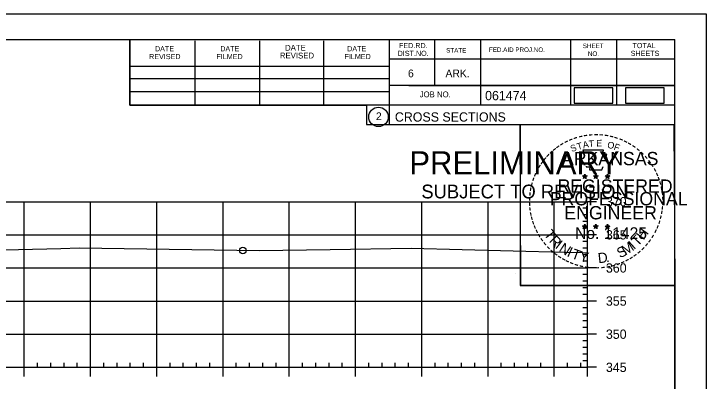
# Model space of a CAD drawing. Extents: x 1359801 to 1362404, y 372415 to 374228.
# Drawn here: x 1361262.1 to 1361366.6, y 373105.8 to 373161.3 of the extents above; entities that cross this region are included whole.
import ezdxf

# ---------------------------------------------------------------- set-up
doc = ezdxf.new("R2010")
doc.units = 0
for name, color, linetype in [('S_DRG_PT_SYM', 7, 'Continuous'), ('S_MAILBOX', 7, 'Continuous'), ('S_PRIMARY_CTL', 7, 'Continuous'), ('S_PRIMARY_CTL_ANNOT', 7, 'Continuous'), ('S_SHOULDER', 7, 'Continuous'), ('S_TELEPHONE_UTILITIES', 7, 'Continuous'), ('S_UNDERGROUND_CABLE', 7, 'Continuous'), ('S_UTL_PT_SYM', 7, 'Continuous'), ('S_WATER_UTILITIES', 7, 'Continuous')]:
    doc.layers.add(name, color=color, linetype=linetype)

msp = doc.modelspace()

# ---------------------------------------------------------------- linework, layer by layer
at = {"layer": 'S_DRG_PT_SYM'}
msp.add_lwpolyline([(1361245.69, 373125.3), (1361269.23, 373125.87), (1361272.01, 373125.94), (1361275.39, 373125.89), (1361299.18, 373125.53), (1361309.87, 373125.71), (1361322.12, 373125.9), (1361345.23, 373125.31), (1361347.93, 373125.24), (1361348.33, 373125.22), (1361348.71, 373125.21)], dxfattribs=at)
at = {"layer": 'S_MAILBOX'}
for p, q in [((1361058.71, 373132.92), (1361348.71, 373132.92)), ((1361058.71, 373132.92), (1361348.71, 373132.92)), ((1361263.71, 373107.92), (1361263.71, 373132.92)), ((1361263.71, 373107.92), (1361263.71, 373132.92)), ((1361273.71, 373107.92), (1361273.71, 373132.92)), ((1361273.71, 373107.92), (1361273.71, 373132.92)), ((1361283.71, 373107.92), (1361283.71, 373132.92)), ((1361283.71, 373107.92), (1361283.71, 373132.92)), ((1361293.71, 373107.92), (1361293.71, 373132.92)), ((1361293.71, 373107.92), (1361293.71, 373132.92)), ((1361303.71, 373107.92), (1361303.71, 373132.92)), ((1361303.71, 373107.92), (1361303.71, 373132.92)), ((1361313.71, 373107.92), (1361313.71, 373132.92)), ((1361313.71, 373107.92), (1361313.71, 373132.92)), ((1361323.71, 373107.92), (1361323.71, 373132.92)), ((1361323.71, 373107.92), (1361323.71, 373132.92)), ((1361333.71, 373107.92), (1361333.71, 373132.92)), ((1361333.71, 373107.92), (1361333.71, 373132.92)), ((1361343.71, 373107.92), (1361343.71, 373132.92)), ((1361343.71, 373107.92), (1361343.71, 373132.92)), ((1361348.71, 373107.92), (1361348.71, 373132.92)), ((1361348.71, 373107.92), (1361348.71, 373132.92)), ((1361058.71, 373127.92), (1361348.71, 373127.92)), ((1361058.71, 373127.92), (1361348.71, 373127.92)), ((1361058.71, 373122.92), (1361348.71, 373122.92)), ((1361058.71, 373122.92), (1361348.71, 373122.92)), ((1361058.71, 373117.92), (1361348.71, 373117.92)), ((1361058.71, 373117.92), (1361348.71, 373117.92)), ((1361058.71, 373112.92), (1361348.71, 373112.92)), ((1361058.71, 373112.92), (1361348.71, 373112.92)), ((1361058.71, 373107.92), (1361348.71, 373107.92)), ((1361058.71, 373107.92), (1361348.71, 373107.92))]:
    msp.add_line(p, q, dxfattribs=at)
at = {"layer": 'S_SHOULDER'}
for p, q in [((1361033.31, 373161.28), (1361366.64, 373161.28)), ((1361337.92, 373122.13), (1361337.92, 373122.13))]:
    msp.add_line(p, q, dxfattribs=at)
for points in [[(1361033.3, 373161.28), (1361366.64, 373161.28), (1361366.64, 372947.94), (1361033.3, 372947.94)], [(1361279.63, 373157.38), (1361279.63, 373147.5), (1361315.36, 373147.5), (1361315.36, 373144.58), (1361338.56, 373144.58), (1361338.56, 373120.25), (1361361.89, 373120.25), (1361361.89, 372951.92), (1361045.71, 372951.92), (1361045.71, 373157.38)], [(1361338.56, 373144.58), (1361361.77, 373144.58), (1361361.89, 373120.25), (1361338.68, 373120.25)]]:
    msp.add_lwpolyline(points, close=True, dxfattribs=at)
msp.add_circle((1361296.69, 373125.57), 0.5, dxfattribs=at)
at = {"layer": 'S_TELEPHONE_UTILITIES'}
for p, q in [((1361347.98, 373136.84), (1361348.32, 373136.73)), ((1361347.98, 373136.84), (1361348.23, 373136.79)), ((1361347.98, 373136.84), (1361348.21, 373136.71)), ((1361348.11, 373136.43), (1361348.32, 373136.73)), ((1361348.11, 373136.43), (1361348.23, 373136.67)), ((1361348.11, 373136.43), (1361348.32, 373136.65)), ((1361348.32, 373137.09), (1361348.28, 373136.84)), ((1361348.32, 373136.73), (1361348.32, 373137.09)), ((1361348.32, 373137.09), (1361348.37, 373136.84)), ((1361348.67, 373136.84), (1361348.32, 373136.73)), ((1361348.54, 373136.43), (1361348.32, 373136.73)), ((1361348.54, 373136.43), (1361348.32, 373136.64)), ((1361348.67, 373136.84), (1361348.39, 373136.79)), ((1361348.54, 373136.43), (1361348.4, 373136.72)), ((1361348.67, 373136.84), (1361348.47, 373136.73)), ((1361349.65, 373136.84), (1361349.99, 373136.73)), ((1361349.65, 373136.84), (1361349.9, 373136.79)), ((1361349.65, 373136.84), (1361349.88, 373136.71)), ((1361349.78, 373136.43), (1361349.99, 373136.73)), ((1361349.78, 373136.43), (1361349.9, 373136.67)), ((1361349.78, 373136.43), (1361349.99, 373136.65)), ((1361349.99, 373137.09), (1361349.95, 373136.84)), ((1361349.99, 373136.73), (1361349.99, 373137.09)), ((1361349.99, 373137.09), (1361350.04, 373136.84)), ((1361350.34, 373136.84), (1361349.99, 373136.73)), ((1361350.21, 373136.43), (1361349.99, 373136.73)), ((1361350.21, 373136.43), (1361349.99, 373136.64)), ((1361350.34, 373136.84), (1361350.06, 373136.79)), ((1361350.21, 373136.43), (1361350.07, 373136.72)), ((1361350.34, 373136.84), (1361350.14, 373136.73)), ((1361351.41, 373136.82), (1361351.76, 373136.71)), ((1361351.41, 373136.82), (1361351.66, 373136.78)), ((1361351.41, 373136.82), (1361351.65, 373136.7)), ((1361351.54, 373136.42), (1361351.76, 373136.71)), ((1361351.54, 373136.42), (1361351.67, 373136.66)), ((1361351.54, 373136.42), (1361351.76, 373136.63)), ((1361351.76, 373137.08), (1361351.72, 373136.83)), ((1361351.76, 373136.71), (1361351.76, 373137.08)), ((1361351.76, 373137.08), (1361351.81, 373136.83)), ((1361352.11, 373136.82), (1361351.76, 373136.71)), ((1361351.97, 373136.42), (1361351.76, 373136.71)), ((1361351.97, 373136.42), (1361351.76, 373136.63)), ((1361352.11, 373136.82), (1361351.82, 373136.78)), ((1361351.97, 373136.42), (1361351.83, 373136.71)), ((1361352.11, 373136.82), (1361351.9, 373136.72)), ((1361347.97, 373129.26), (1361348.32, 373129.15)), ((1361347.97, 373129.26), (1361348.22, 373129.22)), ((1361347.97, 373129.26), (1361348.21, 373129.14)), ((1361348.1, 373128.86), (1361348.32, 373129.15)), ((1361348.1, 373128.86), (1361348.23, 373129.1)), ((1361348.32, 373129.52), (1361348.28, 373129.27)), ((1361348.32, 373129.15), (1361348.32, 373129.52)), ((1361348.32, 373129.52), (1361348.37, 373129.27)), ((1361348.67, 373129.26), (1361348.32, 373129.15)), ((1361348.53, 373128.86), (1361348.32, 373129.15)), ((1361348.67, 373129.26), (1361348.38, 373129.21)), ((1361348.53, 373128.86), (1361348.4, 373129.15)), ((1361348.67, 373129.26), (1361348.46, 373129.16)), ((1361349.64, 373129.26), (1361349.99, 373129.15)), ((1361349.64, 373129.26), (1361349.89, 373129.22)), ((1361349.64, 373129.26), (1361349.88, 373129.14)), ((1361349.77, 373128.86), (1361349.99, 373129.15)), ((1361349.77, 373128.86), (1361349.9, 373129.1)), ((1361349.99, 373129.52), (1361349.95, 373129.27)), ((1361349.99, 373129.15), (1361349.99, 373129.52)), ((1361349.99, 373129.52), (1361350.04, 373129.27)), ((1361350.34, 373129.26), (1361349.99, 373129.15)), ((1361350.2, 373128.86), (1361349.99, 373129.15)), ((1361350.34, 373129.26), (1361350.05, 373129.21)), ((1361350.2, 373128.86), (1361350.07, 373129.15)), ((1361350.34, 373129.26), (1361350.13, 373129.16)), ((1361351.41, 373129.25), (1361351.76, 373129.14)), ((1361351.41, 373129.25), (1361351.66, 373129.21)), ((1361351.41, 373129.25), (1361351.64, 373129.13)), ((1361351.54, 373128.85), (1361351.76, 373129.14)), ((1361351.76, 373129.51), (1361351.72, 373129.26)), ((1361351.76, 373129.14), (1361351.76, 373129.51)), ((1361351.76, 373129.51), (1361351.81, 373129.26)), ((1361352.1, 373129.25), (1361351.76, 373129.14)), ((1361351.97, 373128.85), (1361351.76, 373129.14)), ((1361352.1, 373129.25), (1361351.82, 373129.2)), ((1361351.97, 373128.85), (1361351.83, 373129.14)), ((1361352.1, 373129.25), (1361351.9, 373129.15)), ((1361348.1, 373128.86), (1361348.32, 373129.07)), ((1361348.53, 373128.86), (1361348.32, 373129.07)), ((1361349.77, 373128.86), (1361349.99, 373129.07)), ((1361350.2, 373128.86), (1361349.99, 373129.07)), ((1361351.54, 373128.85), (1361351.67, 373129.09)), ((1361351.54, 373128.85), (1361351.75, 373129.06)), ((1361351.97, 373128.85), (1361351.75, 373129.06))]:
    msp.add_line(p, q, dxfattribs=at)
for points in [[(1361348.02, 373140.71), (1361348.29, 373139.89)], [(1361351.53, 373139.79), (1361351.67, 373140.08), (1361350.98, 373140.05), (1361351.13, 373140.71), (1361348.02, 373140.71)], [(1361348.51, 373138.29), (1361348.51, 373138.2), (1361349.07, 373138.19), (1361349.02, 373137.71), (1361350.89, 373137.71), (1361351.09, 373138.25)], [(1361348.32, 373137.09), (1361348.54, 373136.43), (1361347.98, 373136.84), (1361348.67, 373136.84), (1361348.11, 373136.43), (1361348.32, 373137.09)], [(1361349.99, 373137.09), (1361350.21, 373136.43), (1361349.65, 373136.84), (1361350.34, 373136.84), (1361349.78, 373136.43), (1361349.99, 373137.09)], [(1361351.76, 373137.08), (1361351.97, 373136.42), (1361351.41, 373136.82), (1361352.11, 373136.82), (1361351.54, 373136.42), (1361351.76, 373137.08)], [(1361348.32, 373129.52), (1361348.53, 373128.86), (1361347.97, 373129.26), (1361348.67, 373129.26), (1361348.1, 373128.86), (1361348.32, 373129.52)], [(1361349.99, 373129.52), (1361350.2, 373128.86), (1361349.64, 373129.26), (1361350.34, 373129.26), (1361349.77, 373128.86), (1361349.99, 373129.52)], [(1361351.76, 373129.51), (1361351.97, 373128.85), (1361351.41, 373129.25), (1361352.1, 373129.25), (1361351.54, 373128.85), (1361351.76, 373129.51)]]:
    msp.add_lwpolyline(points, dxfattribs=at)
for centre, radius in [((1361348.32, 373136.73), 0.172), ((1361348.32, 373136.73), 0.145), ((1361348.32, 373136.73), 0.116), ((1361348.32, 373136.73), 0.0991), ((1361348.32, 373136.73), 0.0747), ((1361348.32, 373136.73), 0.0495), ((1361348.32, 373136.73), 0.0296), ((1361349.99, 373136.73), 0.172), ((1361349.99, 373136.73), 0.145), ((1361349.99, 373136.73), 0.116), ((1361349.99, 373136.73), 0.0991), ((1361349.99, 373136.73), 0.0747), ((1361349.99, 373136.73), 0.0495), ((1361349.99, 373136.73), 0.0296), ((1361351.76, 373136.71), 0.172), ((1361351.76, 373136.71), 0.145), ((1361351.76, 373136.71), 0.116), ((1361351.76, 373136.71), 0.0991), ((1361351.76, 373136.71), 0.0747), ((1361351.76, 373136.71), 0.0495), ((1361351.76, 373136.71), 0.0296), ((1361348.32, 373129.15), 0.172), ((1361348.32, 373129.15), 0.145), ((1361348.32, 373129.15), 0.116), ((1361348.32, 373129.15), 0.0991), ((1361348.32, 373129.15), 0.0747), ((1361348.32, 373129.15), 0.0495), ((1361348.32, 373129.15), 0.0296), ((1361349.99, 373129.15), 0.172), ((1361349.99, 373129.15), 0.145), ((1361349.99, 373129.15), 0.116), ((1361349.99, 373129.15), 0.0991), ((1361349.99, 373129.15), 0.0747), ((1361349.99, 373129.15), 0.0495), ((1361349.99, 373129.15), 0.0296), ((1361351.76, 373129.14), 0.172), ((1361351.76, 373129.14), 0.145), ((1361351.76, 373129.14), 0.116), ((1361351.76, 373129.14), 0.0991), ((1361351.76, 373129.14), 0.0747), ((1361351.76, 373129.14), 0.0495), ((1361351.76, 373129.14), 0.0296)]:
    msp.add_circle(centre, radius, dxfattribs=at)
at = {"layer": 'S_UNDERGROUND_CABLE'}
for points in [[(1361346.74, 373147.81), (1361352.57, 373147.81), (1361352.57, 373150.12), (1361346.74, 373150.12)], [(1361354.47, 373147.81), (1361360.3, 373147.81), (1361360.3, 373150.12), (1361354.47, 373150.12)]]:
    msp.add_lwpolyline(points, close=True, dxfattribs=at)
at = {"layer": 'S_UTL_PT_SYM'}
for p, q in [((1361045.71, 373157.38), (1361361.89, 373157.38)), ((1361279.63, 373147.5), (1361279.63, 373157.38)), ((1361318.79, 373157.38), (1361318.79, 373144.58)), ((1361325.63, 373157.38), (1361325.63, 373150.44)), ((1361332.57, 373157.38), (1361332.57, 373147.5)), ((1361346.15, 373157.38), (1361346.15, 373147.5)), ((1361353.09, 373157.38), (1361353.09, 373147.5)), ((1361361.89, 372951.92), (1361361.89, 373157.38)), ((1361289.49, 373147.5), (1361289.49, 373157.18)), ((1361299.25, 373147.5), (1361299.25, 373157.18)), ((1361308.93, 373147.5), (1361308.93, 373157.18)), ((1361361.89, 373154.44), (1361318.79, 373154.44)), ((1361361.89, 373154.46), (1361361.89, 373154.46)), ((1361279.63, 373153.36), (1361318.79, 373153.36)), ((1361279.63, 373151.5), (1361318.79, 373151.5)), ((1361361.89, 373150.44), (1361318.79, 373150.44)), ((1361321.75, 373150.44), (1361361.89, 373150.44)), ((1361279.63, 373147.5), (1361279.63, 373149.56)), ((1361279.63, 373149.56), (1361318.79, 373149.56)), ((1361361.89, 373147.5), (1361279.63, 373147.5)), ((1361318.79, 373144.58), (1361361.89, 373144.58))]:
    msp.add_line(p, q, dxfattribs=at)
msp.add_circle((1361317.18, 373145.72), 1.47, dxfattribs=at)
at = {"layer": 'S_WATER_UTILITIES'}
for p, q in [((1361348.71, 373107.92), (1361348.71, 373132.92)), ((1361350.11, 373132.92), (1361348.71, 373132.92)), ((1361348.71, 373131.92), (1361348.01, 373131.92)), ((1361348.71, 373130.92), (1361348.01, 373130.92)), ((1361348.71, 373129.92), (1361348.01, 373129.92)), ((1361348.71, 373128.92), (1361348.01, 373128.92)), ((1361350.11, 373127.92), (1361348.71, 373127.92)), ((1361348.71, 373126.92), (1361348.01, 373126.92)), ((1361348.71, 373125.92), (1361348.01, 373125.92)), ((1361348.71, 373124.92), (1361348.01, 373124.92)), ((1361348.71, 373123.92), (1361348.01, 373123.92)), ((1361350.11, 373122.92), (1361348.71, 373122.92)), ((1361348.71, 373121.92), (1361348.01, 373121.92)), ((1361348.71, 373120.92), (1361348.01, 373120.92)), ((1361348.71, 373119.92), (1361348.01, 373119.92)), ((1361348.71, 373118.92), (1361348.01, 373118.92)), ((1361350.11, 373117.92), (1361348.71, 373117.92)), ((1361348.71, 373116.92), (1361348.01, 373116.92)), ((1361348.71, 373115.92), (1361348.01, 373115.92)), ((1361348.71, 373114.92), (1361348.01, 373114.92)), ((1361348.71, 373113.92), (1361348.01, 373113.92)), ((1361350.11, 373112.92), (1361348.71, 373112.92)), ((1361348.71, 373111.92), (1361348.01, 373111.92)), ((1361348.71, 373110.92), (1361348.01, 373110.92)), ((1361348.71, 373109.92), (1361348.01, 373109.92)), ((1361265.71, 373107.92), (1361265.71, 373108.62)), ((1361267.71, 373107.92), (1361267.71, 373108.62)), ((1361269.71, 373107.92), (1361269.71, 373108.62)), ((1361271.71, 373107.92), (1361271.71, 373108.62)), ((1361275.71, 373107.92), (1361275.71, 373108.62)), ((1361277.71, 373107.92), (1361277.71, 373108.62)), ((1361279.71, 373107.92), (1361279.71, 373108.62)), ((1361281.71, 373107.92), (1361281.71, 373108.62)), ((1361285.71, 373107.92), (1361285.71, 373108.62)), ((1361287.71, 373107.92), (1361287.71, 373108.62)), ((1361289.71, 373107.92), (1361289.71, 373108.62)), ((1361291.71, 373107.92), (1361291.71, 373108.62)), ((1361295.71, 373107.92), (1361295.71, 373108.62)), ((1361297.71, 373107.92), (1361297.71, 373108.62)), ((1361299.71, 373107.92), (1361299.71, 373108.62)), ((1361301.71, 373107.92), (1361301.71, 373108.62)), ((1361305.71, 373107.92), (1361305.71, 373108.62)), ((1361307.71, 373107.92), (1361307.71, 373108.62)), ((1361309.71, 373107.92), (1361309.71, 373108.62)), ((1361311.71, 373107.92), (1361311.71, 373108.62)), ((1361315.71, 373107.92), (1361315.71, 373108.62)), ((1361317.71, 373107.92), (1361317.71, 373108.62)), ((1361319.71, 373107.92), (1361319.71, 373108.62)), ((1361321.71, 373107.92), (1361321.71, 373108.62)), ((1361325.71, 373107.92), (1361325.71, 373108.62)), ((1361327.71, 373107.92), (1361327.71, 373108.62)), ((1361329.71, 373107.92), (1361329.71, 373108.62)), ((1361331.71, 373107.92), (1361331.71, 373108.62)), ((1361335.71, 373107.92), (1361335.71, 373108.62)), ((1361337.71, 373107.92), (1361337.71, 373108.62)), ((1361339.71, 373107.92), (1361339.71, 373108.62)), ((1361341.71, 373107.92), (1361341.71, 373108.62)), ((1361345.71, 373107.92), (1361345.71, 373108.62)), ((1361347.71, 373107.92), (1361347.71, 373108.62)), ((1361348.71, 373108.92), (1361348.01, 373108.92)), ((1361058.71, 373107.92), (1361348.71, 373107.92)), ((1361263.71, 373106.52), (1361263.71, 373107.92)), ((1361273.71, 373106.52), (1361273.71, 373107.92)), ((1361283.71, 373106.52), (1361283.71, 373107.92)), ((1361293.71, 373106.52), (1361293.71, 373107.92)), ((1361303.71, 373106.52), (1361303.71, 373107.92)), ((1361313.71, 373106.52), (1361313.71, 373107.92)), ((1361323.71, 373106.52), (1361323.71, 373107.92)), ((1361333.71, 373106.52), (1361333.71, 373107.92)), ((1361343.71, 373106.52), (1361343.71, 373107.92)), ((1361348.71, 373106.52), (1361348.71, 373107.92)), ((1361350.11, 373107.92), (1361348.71, 373107.92))]:
    msp.add_line(p, q, dxfattribs=at)

# ---------------------------------------------------------------- texts
at = {"layer": 'S_PRIMARY_CTL'}
for s, p in [('370', (1361351.51, 373132.22)), ('365', (1361351.51, 373127.22)), ('360', (1361351.51, 373122.22)), ('355', (1361351.51, 373117.22)), ('350', (1361351.51, 373112.22)), ('345', (1361351.51, 373107.22))]:
    msp.add_text(s, height=1.4, dxfattribs=at).set_placement(p)
at = {"layer": 'S_PRIMARY_CTL_ANNOT'}
for s, height, p in [('PRELIMINARY', 3.5, (1361321.84, 373137.04)), ('DWB', 0.01, (1361322.59, 373138.89)), ('SUBJECT TO REVISION', 2.0751, (1361323.65, 373133.42))]:
    msp.add_text(s, height=height, rotation=360, dxfattribs=at).set_placement(p)
at = {"layer": 'S_SHOULDER'}
msp.add_text('+', height=0.1, dxfattribs=at).set_placement((1361347.88, 373125.19))
at = {"layer": 'S_TELEPHONE_UTILITIES'}
for s, height, rotation, p in [('-', 1.6, 19.1761, (1361346.76, 373141.84)), ('-', 1.6, 13.6301, (1361347.51, 373142.08)), ('-', 1.6, 10.2193, (1361348.19, 373142.24)), ('-', 1.6, 5.8968, (1361348.92, 373142.35)), ('-', 1.6, 0.1862, (1361349.69, 373142.43)), ('-', 1.6, 357.743, (1361350.42, 373142.41)), ('-', 1.6, 352.1617, (1361351.16, 373142.36)), ('-', 1.6, 347.2049, (1361351.88, 373142.24)), ('-', 1.6, 342.3362, (1361352.51, 373142.09)), ('-', 1.6, 34.0636, (1361344.9, 373140.89)), ('-', 1.6, 28.7918, (1361345.5, 373141.26)), ('-', 1.6, 24.3072, (1361346.13, 373141.57)), ('T', 1, 16.4036, (1361347.28, 373140.72)), ('A', 1, 11.2132, (1361348.11, 373140.97)), ('T', 1, 6.0228, (1361348.96, 373141.14)), ('E', 1, 0.8323, (1361350.06, 373141.25)), ('O', 1, 350.4515, (1361351.67, 373141.04)), ('F', 1, 340.0707, (1361352.62, 373140.81)), ('-', 1.6, 337.8551, (1361353.25, 373141.87)), ('-', 1.6, 334.1211, (1361353.88, 373141.59)), ('-', 1.6, 329.6409, (1361354.46, 373141.31)), ('-', 1.6, 42.9622, (1361343.41, 373139.7)), ('-', 1.6, 38.9507, (1361343.85, 373140.11)), ('-', 1.6, 36.2317, (1361344.32, 373140.49)), ('S', 1, 21.594, (1361346.37, 373140.39)), ('-', 1.6, 325.8627, (1361355.1, 373140.95)), ('-', 1.6, 320.5297, (1361355.71, 373140.52)), ('-', 1.6, 50.6142, (1361342.56, 373138.73)), ('-', 1.6, 48.423, (1361342.96, 373139.22)), ('ARKANSAS', 2, 360, (1361344.87, 373138.43)), ('-', 1.6, 315.5786, (1361356.31, 373140.04)), ('-', 1.6, 309.8797, (1361356.88, 373139.49)), ('-', 1.6, 58.0706, (1361341.82, 373137.64)), ('-', 1.6, 54.2325, (1361342.15, 373138.16)), ('-', 1.6, 306.6522, (1361357.4, 373138.88)), ('-', 1.4, 303.6753, (1361357.89, 373138.32)), ('-', 1.6, 62.8713, (1361341.51, 373137.02)), ('-', 1.6, 299.6684, (1361358.21, 373137.71)), ('-', 1.6, 72.3945, (1361341.03, 373135.78)), ('-', 1.6, 67.7743, (1361341.25, 373136.41)), ('DWB', 0.01, 360, (1361348.31, 373136.72)), ('DWB', 0.01, 360, (1361349.98, 373136.72)), ('DWB', 0.01, 360, (1361351.75, 373136.71)), ('-', 1.6, 294.6628, (1361358.53, 373137.1)), ('-', 1.6, 290.5728, (1361358.79, 373136.52)), ('-', 1.6, 75.461, (1361340.84, 373135.07)), ('REGISTERED', 2, 360, (1361344.19, 373134.28)), ('-', 1.6, 285.1233, (1361359.02, 373135.94)), ('-', 1.6, 85.1863, (1361340.63, 373133.66)), ('-', 1.6, 81.2013, (1361340.7, 373134.36)), ('PROFESSIONAL', 2, 360, (1361343.04, 373132.37)), ('-', 1.6, 280.5493, (1361359.22, 373135.2)), ('-', 1.6, 276.5962, (1361359.39, 373134.43)), ('-', 1.6, 89.0622, (1361340.6, 373132.96)), ('-', 1.6, 274.3301, (1361359.45, 373133.71)), ('-', 1.6, 94.1959, (1361340.64, 373132.24)), ('ENGINEER', 2, 360, (1361345.23, 373130.25)), ('-', 1.6, 263.5172, (1361359.46, 373132.41)), ('-', 1.6, 269.9407, (1361359.48, 373133.08)), ('-', 1.6, 98.9479, (1361340.71, 373131.57)), ('-', 1.6, 101.7149, (1361340.84, 373130.84)), ('-', 1.6, 260.9953, (1361359.39, 373131.76)), ('-', 1.6, 105.4578, (1361341.01, 373130.24)), ('-', 1.6, 255.7626, (1361359.28, 373131.08)), ('-', 1.6, 109.0874, (1361341.22, 373129.61)), ('-', 1.6, 114.0643, (1361341.48, 373129.02)), ('DWB', 0.01, 360, (1361348.31, 373129.15)), ('DWB', 0.01, 360, (1361349.98, 373129.15)), ('DWB', 0.01, 360, (1361351.74, 373129.14)), ('-', 1.6, 247.8887, (1361358.88, 373129.69)), ('-', 1.6, 252.8681, (1361359.1, 373130.36)), ('-', 1.6, 115.7289, (1361341.78, 373128.4)), ('-', 1.6, 120.4471, (1361342.14, 373127.81)), ('T', 1.54, 306.0406, (1361342.08, 373127.99)), ('No. 11425', 1.757, 360, (1361346.86, 373127.3)), ('H', 1.54, 54.6088, (1361357.2, 373127.03)), ('-', 1.6, 244.6197, (1361358.61, 373129.06)), ('-', 1.6, 125.8934, (1361342.54, 373127.25)), ('R', 1.54, 314.005, (1361342.84, 373126.94)), ('I', 1.54, 321.9694, (1361343.74, 373126.01)), ('I', 1.54, 42.1136, (1361355.75, 373125.61)), ('T', 1.54, 46.6444, (1361356.31, 373126.08)), ('-', 1.6, 233.8452, (1361357.82, 373127.65)), ('-', 1.6, 239.0712, (1361358.22, 373128.3)), ('-', 1.6, 130.7181, (1361343, 373126.7)), ('-', 1.6, 134.2238, (1361343.52, 373126.15)), ('N', 1.54, 326.5002, (1361344.31, 373125.54)), ('I', 1.54, 335.3603, (1361345.52, 373124.75)), ('S', 1.54, 26.9312, (1361353.63, 373124.35)), ('M', 1.54, 32.6563, (1361354.46, 373124.76)), ('-', 1.6, 225.7653, (1361356.91, 373126.52)), ('-', 1.6, 231.2538, (1361357.39, 373127.09)), ('-', 1.6, 138.9338, (1361344.04, 373125.69)), ('-', 1.6, 144.6463, (1361344.6, 373125.28)), ('T', 1.54, 339.8912, (1361346.18, 373124.43)), ('Y', 1.54, 347.8556, (1361347.4, 373123.98)), ('D', 1.54, 6.3969, (1361350.38, 373123.62)), ('-', 1.6, 215.7363, (1361355.84, 373125.54)), ('-', 1.6, 221.0851, (1361356.39, 373126.01)), ('-', 1.6, 148.0898, (1361345.16, 373124.91)), ('-', 1.6, 151.5704, (1361345.74, 373124.59)), ('-', 1.6, 154.6002, (1361346.26, 373124.34)), ('.', 1.54, 13.7642, (1361351.57, 373123.75)), ('-', 1.6, 204.2516, (1361354.12, 373124.49)), ('-', 1.6, 207.3568, (1361354.75, 373124.81)), ('-', 1.6, 212.2491, (1361355.3, 373125.15)), ('-', 1.6, 158.5612, (1361346.89, 373124.09)), ('-', 1.6, 162.7983, (1361347.57, 373123.87)), ('-', 1.6, 167.5555, (1361348.29, 373123.71)), ('-', 1.6, 173.1155, (1361349.06, 373123.6)), ('-', 1.6, 176.5183, (1361349.81, 373123.55)), ('-', 1.6, 181.5918, (1361350.55, 373123.57)), ('-', 1.6, 185.8167, (1361351.36, 373123.64)), ('-', 1.6, 191.2858, (1361352.1, 373123.77)), ('-', 1.6, 195.4743, (1361352.83, 373123.97)), ('-', 1.6, 200.7184, (1361353.5, 373124.22))]:
    msp.add_text(s, height=height, rotation=rotation, dxfattribs=at).set_placement(p)
at = {"layer": 'S_UTL_PT_SYM'}
for s, height, p in [('DATE', 0.782, (1361283.43, 373155.62)), ('DATE', 0.782, (1361293.29, 373155.62)), ('DATE', 0.879, (1361303.07, 373155.72)), ('DATE', 0.782, (1361312.45, 373155.62)), ('FED.RD.', 0.782, (1361320.27, 373156.1)), ('SHEET', 0.684, (1361348.01, 373156.1)), ('TOTAL', 0.782, (1361355.53, 373156.1)), ('REVISED', 0.782, (1361282.55, 373154.44)), ('FILMED', 0.782, (1361292.71, 373154.44)), ('REVISED', 0.879, (1361302.29, 373154.54)), ('FILMED', 0.782, (1361312.05, 373154.44)), ('DIST.NO.', 0.782, (1361320.07, 373154.92)), ('STATE', 0.684, (1361327.39, 373155.42)), ('FED.AID PROJ.NO.', 0.684, (1361333.85, 373155.52)), ('NO.', 0.684, (1361348.79, 373154.92)), ('SHEETS', 0.782, (1361355.25, 373154.92)), ('6', 1.17, (1361321.63, 373151.7)), ('ARK.', 1.172, (1361327.29, 373151.7)), ('JOB NO.', 0.879, (1361323.39, 373148.68)), ('061474', 1.4, (1361333.27, 373148.24)), ('2', 1.17, (1361316.79, 373145.23)), ('CROSS SECTIONS', 1.4, (1361319.65, 373145.01))]:
    msp.add_text(s, height=height, rotation=360, dxfattribs=at).set_placement(p)

doc.saveas('drawing.dxf')
